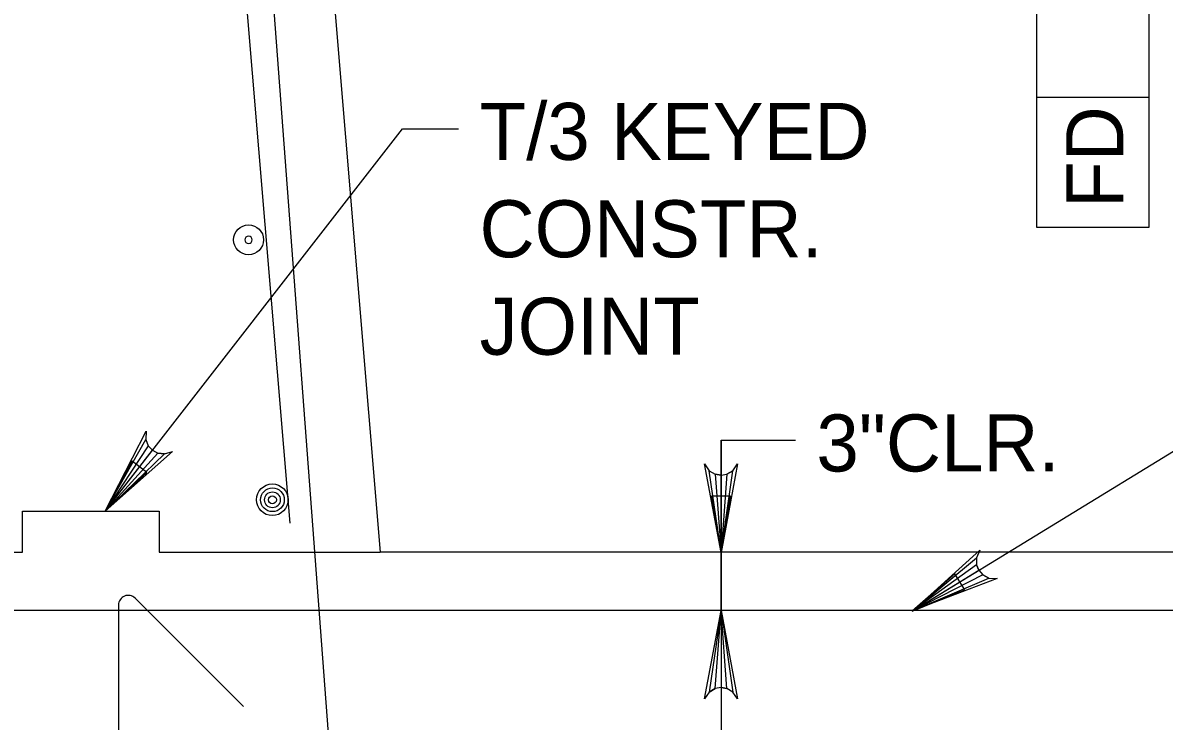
# Model space of a CAD drawing. Extents: x 638340 to 640242, y 295465 to 298435.
# Drawn here: x 639137.8 to 639197.8, y 296457.2 to 296494 of the extents above; entities that cross this region are included whole.
import ezdxf

# ---------------------------------------------------------------- set-up
doc = ezdxf.new("R2010")
doc.units = 0
for name, color, linetype in [('3', 7, 'Continuous'), ('Level 3', 7, 'Continuous'), ('Level 4', 7, 'Continuous'), ('Level 6', 7, 'Continuous'), ('Level 7', 7, 'Continuous'), ('Level 9', 7, 'Continuous')]:
    doc.layers.add(name, color=color, linetype=linetype)

# ---------------------------------------------------------------- blocks, each defined once
blk = doc.blocks.new('B')
at = {"layer": '3'}
blk.add_circle((0, 0), 0.16, dxfattribs=at)
for start, end in [(0, 180), (180, 0)]:
    blk.add_arc((0, 0), 0.0391, start, end, dxfattribs=at)

msp = doc.modelspace()

# ---------------------------------------------------------------- linework, layer by layer
at = {"layer": 'Level 4'}
for p, q in [((639191.099, 296483.211), (639191.099, 296518.443)), ((639196.994, 296518.443), (639196.994, 296483.211)), ((639196.994, 296490.041), (639191.099, 296490.041)), ((639142.086, 296468.281), (639157.727, 296488.394)), ((639157.727, 296488.394), (639160.674, 296488.394)), ((639196.994, 296483.211), (639191.099, 296483.211)), ((639184.583, 296463.05), (639203.752, 296474.791)), ((639184.583, 296463.05), (639203.752, 296474.791)), ((639174.484, 296472.008), (639174.484, 296454.841)), ((639174.485, 296463.051), (639174.485, 296472.009)), ((639174.485, 296472.009), (639178.398, 296472.009))]:
    msp.add_line(p, q, dxfattribs=at)
for points in [[(639142.086, 296468.281), (639144.253, 296472.487), (639144.23, 296472.053), (639144.361, 296471.716), (639144.575, 296471.481), (639144.854, 296471.333), (639145.214, 296471.288), (639145.63, 296471.416), (639142.086, 296468.281), (639145.214, 296471.288), (639144.854, 296471.333), (639142.086, 296468.281), (639144.575, 296471.481), (639144.361, 296471.716), (639142.086, 296468.281), (639144.23, 296472.053)], [(639174.485, 296466.114), (639173.614, 296470.766), (639173.861, 296470.408), (639174.173, 296470.223), (639174.485, 296470.169), (639174.797, 296470.223), (639175.109, 296470.408), (639175.356, 296470.766), (639174.485, 296466.114), (639175.109, 296470.408), (639174.797, 296470.223), (639174.485, 296466.114), (639174.485, 296470.169), (639174.173, 296470.223), (639174.485, 296466.114), (639173.861, 296470.408)], [(639174.485, 296466.114), (639173.614, 296470.766), (639173.861, 296470.408), (639174.173, 296470.223), (639174.485, 296470.169), (639174.797, 296470.223), (639175.109, 296470.408), (639175.356, 296470.766), (639174.485, 296466.114), (639175.109, 296470.408), (639174.797, 296470.223), (639174.485, 296466.114), (639174.485, 296470.169), (639174.173, 296470.223), (639174.485, 296466.114), (639173.861, 296470.408)], [(639184.584, 296463.051), (639188.096, 296466.224), (639187.92, 296465.825), (639187.924, 296465.463), (639188.042, 296465.168), (639188.25, 296464.931), (639188.571, 296464.762), (639189.007, 296464.738), (639184.584, 296463.051), (639188.571, 296464.762), (639188.25, 296464.931), (639184.584, 296463.051), (639188.042, 296465.168), (639187.924, 296465.463), (639184.584, 296463.051), (639187.92, 296465.825)], [(639184.584, 296463.051), (639188.096, 296466.224), (639187.92, 296465.825), (639187.924, 296465.463), (639188.042, 296465.168), (639188.25, 296464.931), (639188.571, 296464.762), (639189.007, 296464.738), (639184.584, 296463.051), (639188.571, 296464.762), (639188.25, 296464.931), (639184.584, 296463.051), (639188.042, 296465.168), (639187.924, 296465.463), (639184.584, 296463.051), (639187.92, 296465.825)], [(639174.485, 296463.051), (639175.356, 296458.4), (639175.109, 296458.757), (639174.797, 296458.942), (639174.485, 296458.996), (639174.173, 296458.942), (639173.861, 296458.757), (639173.614, 296458.4), (639174.485, 296463.051), (639173.861, 296458.757), (639174.173, 296458.942), (639174.485, 296463.051), (639174.485, 296458.996), (639174.797, 296458.942), (639174.485, 296463.051), (639175.109, 296458.757)]]:
    msp.add_lwpolyline(points, dxfattribs=at)
for points in [[(639144.282, 296470.306), (639143.507, 296470.909), (639142.086, 296468.281)], [(639174.976, 296469.061), (639173.992, 296469.061), (639174.485, 296466.114)], [(639174.976, 296469.061), (639173.992, 296469.061), (639174.485, 296466.114)], [(639187.3, 296464.137), (639186.786, 296464.975), (639184.53, 296463.016)], [(639187.3, 296464.137), (639186.786, 296464.975), (639184.53, 296463.016)]]:
    msp.add_lwpolyline(points, close=True, dxfattribs=at)
at = {"layer": 'Level 6'}
for p, q in [((639148.258, 296510.182), (639151.801, 296467.657)), ((639149.776, 296510.436), (639154.916, 296441.96)), ((639142.793, 296463.34), (639142.793, 296438.993)), ((639149.36, 296458.009), (639143.667, 296463.702)), ((639206.875, 296463.051), (639099.251, 296463.051))]:
    msp.add_line(p, q, dxfattribs=at)
for radius in [0.832, 0.624, 0.416, 0.208]:
    msp.add_circle((639150.888, 296468.878), radius, dxfattribs=at)
msp.add_arc((639143.303, 296463.339), 0.511, 45, 180, dxfattribs=at)
at = {"layer": 'Level 7'}
msp.add_lwpolyline([(639126.734, 296466.122), (639137.745, 296466.122), (639137.745, 296468.281), (639144.923, 296468.281), (639144.923, 296466.122), (639156.55, 296466.122)], dxfattribs=at)
at = {"layer": 'Level 9'}
for p in [(639145.218, 296602.113), (639210.09, 296466.122), (639210.09, 296466.122), (639210.09, 296466.122)]:
    msp.add_line(p, (639156.55, 296466.122), dxfattribs=at)

# ---------------------------------------------------------------- block references
at = {"layer": 'Level 3', "xscale": 4.911876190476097, "yscale": 4.911876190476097, "rotation": 90}
msp.add_blockref('B', (639149.634, 296482.558), dxfattribs=at)

# ---------------------------------------------------------------- texts
at = {"layer": 'Level 3'}
msp.add_text('3"CLR.', height=3.0001, dxfattribs=at).set_placement((639179.502, 296470.368))
at = {"layer": 'Level 4'}
for s, p in [('T/3 KEYED', (639161.784, 296486.762)), ('CONSTR.', (639161.784, 296481.637)), ('JOINT', (639161.784, 296476.509))]:
    msp.add_text(s, height=3.0001, dxfattribs=at).set_placement(p)
msp.add_text('FD', height=3.0001, rotation=90, dxfattribs=at).set_placement((639195.64, 296484.233))

doc.saveas('drawing.dxf')
